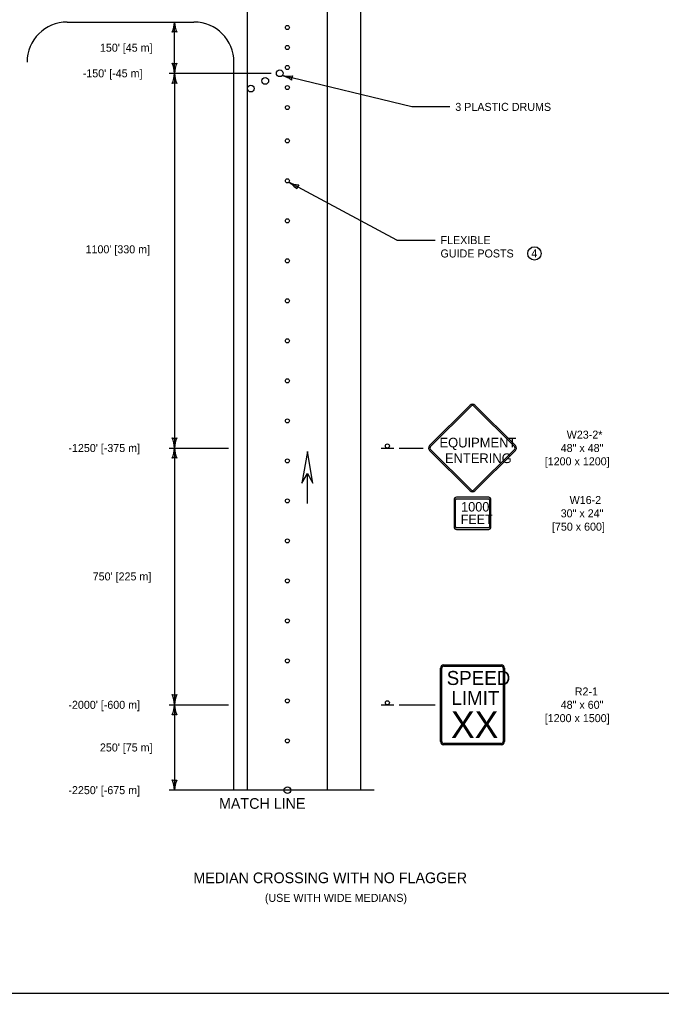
# Model space of a CAD drawing. Extents: x 49991.4 to 50021, y 49987.6 to 50011.4.
# Drawn here: x 50004.22 to 50009.03, y 49987.8 to 49995.1 of the extents above; entities that cross this region are included whole.
import ezdxf

# ---------------------------------------------------------------- set-up
doc = ezdxf.new("R2010")
doc.units = 0
for name, color, linetype in [('Level 1', 7, 'Continuous'), ('Level 2', 7, 'Continuous'), ('Level 3', 7, 'Continuous'), ('Level 6', 7, 'Continuous')]:
    doc.layers.add(name, color=color, linetype=linetype)

msp = doc.modelspace()

# ---------------------------------------------------------------- linework, layer by layer
at = {"layer": 'Level 1'}
for p, q in [((50005.9261, 49989.324), (50005.9261, 49998.3116)), ((50006.5261, 49989.324), (50006.5261, 49998.3116)), ((50006.7761, 49989.324), (50006.7761, 49998.3116)), ((50004.5755, 49995.0842), (50005.5261, 49995.0842)), ((50005.8261, 49989.324), (50005.8261, 49994.7842)), ((50005.3807, 49994.7), (50005.3807, 49993.9384)), ((50007.5963, 49992.2118), (50007.2922, 49991.9078)), ((50007.6033, 49992.2048), (50007.2993, 49991.9006)), ((50007.9286, 49991.9006), (50007.6246, 49992.2048)), ((50007.9357, 49991.9078), (50007.6316, 49992.2118)), ((50006.9281, 49991.89), (50007.0241, 49991.89)), ((50007.2922, 49991.8724), (50007.5963, 49991.5684)), ((50007.2993, 49991.8794), (50007.6033, 49991.5754)), ((50007.6246, 49991.5754), (50007.9286, 49991.8794)), ((50007.6316, 49991.5684), (50007.9357, 49991.8724)), ((50006.3758, 49991.4727), (50006.3758, 49991.6987)), ((50006.3761, 49991.4727), (50006.3761, 49991.6987)), ((50007.4757, 49991.5008), (50007.4757, 49991.2992)), ((50007.4872, 49991.2992), (50007.4872, 49991.5008)), ((50007.735, 49991.521), (50007.493, 49991.521)), ((50007.493, 49991.5076), (50007.735, 49991.5076)), ((50007.7407, 49991.5008), (50007.7407, 49991.2992)), ((50007.7522, 49991.2992), (50007.7522, 49991.5008)), ((50007.735, 49991.2925), (50007.493, 49991.2925)), ((50007.493, 49991.2791), (50007.735, 49991.2791)), ((50007.374, 49989.689), (50007.374, 49990.239)), ((50007.384, 49989.689), (50007.384, 49990.239)), ((50007.399, 49990.264), (50007.829, 49990.264)), ((50007.399, 49990.254), (50007.829, 49990.254)), ((50007.844, 49990.239), (50007.844, 49989.689)), ((50007.854, 49990.239), (50007.854, 49989.689)), ((50006.9281, 49989.964), (50007.0241, 49989.964)), ((50007.829, 49989.674), (50007.399, 49989.674)), ((50007.829, 49989.664), (50007.399, 49989.664))]:
    msp.add_line(p, q, dxfattribs=at)
for points in [[(49999.3835, 49998.9992), (50016.7501, 49998.9992), (50016.7501, 49987.7988), (49999.3835, 49987.7988)], [(50006.4178, 49991.6263), (50006.3761, 49991.8629), (50006.3342, 49991.6263), (50006.3761, 49991.6985)]]:
    msp.add_lwpolyline(points, close=True, dxfattribs=at)
for centre, radius in [((50006.2261, 49995.0436), 0.015), ((50006.2261, 49994.8936), 0.015), ((50006.2261, 49994.7436), 0.015), ((50006.1688, 49994.7), 0.025), ((50006.0605, 49994.6427), 0.025), ((50005.9523, 49994.5853), 0.025), ((50006.2261, 49994.5936), 0.015), ((50006.2261, 49994.4436), 0.015), ((50006.2261, 49994.4436), 0.015), ((50006.2261, 49994.1937), 0.015), ((50006.2261, 49993.8937), 0.015), ((50006.2261, 49993.5937), 0.015), ((50006.2261, 49993.2937), 0.015), ((50006.2261, 49992.9937), 0.015), ((50006.2261, 49992.6937), 0.015), ((50006.2261, 49992.3937), 0.015), ((50006.2261, 49992.0937), 0.015), ((50006.9761, 49991.9052), 0.0152), ((50006.2261, 49991.7937), 0.015), ((50006.2261, 49991.4937), 0.015), ((50006.2261, 49991.1937), 0.015), ((50006.2261, 49990.8937), 0.015), ((50006.2261, 49990.5937), 0.015), ((50006.2261, 49990.2937), 0.015), ((50006.2261, 49989.9937), 0.015), ((50006.2261, 49989.9937), 0.015), ((50006.9761, 49989.9792), 0.0152), ((50006.2261, 49989.6937), 0.015), ((50006.2261, 49989.6937), 0.015), ((50006.2264, 49989.3245), 0.025)]:
    msp.add_circle(centre, radius, dxfattribs=at)
for centre, radius, start, end in [((50004.5755, 49994.7843), 0.3, 90, 180), ((50005.5261, 49994.7843), 0.3, 0, 90), ((50007.614, 49992.1941), 0.025, 45, 135), ((50007.614, 49992.1941), 0.015, 45, 135), ((50007.3099, 49991.89), 0.025, 135, 225), ((50007.3099, 49991.89), 0.015, 135, 225), ((50007.918, 49991.89), 0.015, 315, 45.00024), ((50007.918, 49991.89), 0.025, 315, 45.00024), ((50007.614, 49991.586), 0.025, 225, 314.99957), ((50007.614, 49991.586), 0.015, 225, 314.99957), ((50007.3989, 49990.2389), 0.025, 90, 180), ((50007.3989, 49990.2389), 0.015, 90, 180), ((50007.8289, 49990.2389), 0.025, 0, 90), ((50007.8289, 49990.2389), 0.015, 0, 90), ((50007.3989, 49989.6889), 0.025, 180, 270), ((50007.3989, 49989.6889), 0.015, 180, 270), ((50007.8289, 49989.6889), 0.025, 270, 0), ((50007.8289, 49989.6889), 0.015, 270, 0)]:
    msp.add_arc(centre, radius, start, end, dxfattribs=at)
for centre, major_axis, start_param, end_param in [((50007.493, 49991.5008), (0, 0.0202), 0, 1.570796), ((50007.493, 49991.5008), (0, 0.00672), 0, 1.570796), ((50007.735, 49991.5008), (0, 0.0202), 4.712389, 6.283185), ((50007.735, 49991.5008), (0, 0.00672), 4.712389, 6.283185), ((50007.493, 49991.2992), (0, -0.0202), 4.712389, 6.283185), ((50007.493, 49991.2992), (0, -0.00672), 4.712389, 6.283185), ((50007.735, 49991.2992), (0, -0.00672), 0, 1.570796), ((50007.735, 49991.2992), (0, -0.0202), 0, 1.570796)]:
    msp.add_ellipse(centre, major_axis=major_axis, ratio=0.857375, start_param=start_param, end_param=end_param, dxfattribs=at)
at = {"layer": 'Level 2'}
msp.add_circle((50008.0781, 49993.3493), 0.05, dxfattribs=at)
at = {"layer": 'Level 3'}
for p, q in [((50005.3807, 49994.7), (50005.3807, 49995.0842)), ((50005.3407, 49994.7), (50006.1038, 49994.7)), ((50007.1581, 49994.4483), (50006.1874, 49994.6834)), ((50007.4448, 49994.4483), (50007.1581, 49994.4483)), ((50005.3807, 49993.9384), (50005.3807, 49991.89)), ((50007.0473, 49993.449), (50006.2367, 49993.8831)), ((50007.0473, 49993.449), (50007.3341, 49993.449)), ((50005.3407, 49991.89), (50005.7861, 49991.89)), ((50005.3807, 49991.89), (50005.3807, 49989.964)), ((50007.0641, 49991.89), (50007.2449, 49991.89)), ((50005.3407, 49989.964), (50005.7861, 49989.964)), ((50005.3807, 49989.964), (50005.3807, 49989.324)), ((50007.0641, 49989.964), (50007.334, 49989.964))]:
    msp.add_line(p, q, dxfattribs=at)
for centre, radius, start, end in [((50005.1585, 49995.0934), 0.2223, 337.45601, 357.63952), ((50005.6134, 49995.0957), 0.233, 182.82731, 202.07716), ((50005.3807, 49994.956), 0.0548, 72.13882, 107.86118), ((50005.3807, 49994.8283), 0.0548, 252.13882, 287.86118), ((50005.148, 49994.6886), 0.233, 2.82731, 22.07716), ((50005.6028, 49994.6909), 0.2223, 157.45601, 177.63952), ((50005.1585, 49994.7092), 0.2223, 337.45601, 357.63952), ((50005.6134, 49994.7115), 0.233, 182.82731, 202.07716), ((50005.3807, 49994.5718), 0.0548, 72.13882, 107.86118), ((50006.1262, 49994.4697), 0.2223, 53.83902, 74.02252), ((50006.231, 49994.9123), 0.233, 259.21032, 278.46017), ((50006.312, 49994.6532), 0.0548, 148.52182, 184.24419), ((50006.3318, 49994.084), 0.2223, 244.64868, 264.83219), ((50006.1183, 49993.6824), 0.233, 40.21104, 59.46089), ((50006.3502, 49993.8235), 0.0548, 134.42702, 170.14938), ((50005.3807, 49992.0183), 0.0548, 252.13882, 287.86118), ((50005.148, 49991.8786), 0.233, 2.82731, 22.07716), ((50005.6028, 49991.8809), 0.2223, 157.45601, 177.63952), ((50005.148, 49991.9015), 0.233, 337.92284, 357.17269), ((50005.6028, 49991.8992), 0.2223, 182.36048, 202.54399), ((50005.3807, 49991.7618), 0.0548, 72.13882, 107.86118), ((50005.3807, 49990.0923), 0.0548, 252.13882, 287.86118), ((50005.148, 49989.9526), 0.233, 2.82731, 22.07716), ((50005.6028, 49989.9549), 0.2223, 157.45601, 177.63952), ((50005.1585, 49989.9732), 0.2223, 337.45601, 357.63952), ((50005.6134, 49989.9755), 0.233, 182.82731, 202.07716), ((50005.3807, 49989.8358), 0.0548, 72.13882, 107.86118), ((50005.3807, 49989.4523), 0.0548, 252.13882, 287.86118), ((50005.148, 49989.3126), 0.233, 2.82731, 22.07716), ((50005.6028, 49989.3149), 0.2223, 157.45601, 177.63952)]:
    msp.add_arc(centre, radius, start, end, dxfattribs=at)
at = {"layer": 'Level 6'}
msp.add_line((50006.8761, 49989.324), (50005.3407, 49989.324), dxfattribs=at)

# ---------------------------------------------------------------- texts
at = {"layer": 'Level 1'}
for s, height, p in [('EQUIPMENT', 0.0725, (50007.3662, 49991.8943)), ('ENTERING', 0.0725, (50007.4069, 49991.7769)), ('1000', 0.07124, (50007.5282, 49991.4135)), ('FEET', 0.06989, (50007.5254, 49991.3194)), ('SPEED', 0.10512, (50007.4203, 49990.1127)), ('LIMIT', 0.10512, (50007.4557, 49989.9625)), ('XX', 0.1989, (50007.4525, 49989.7153))]:
    msp.add_text(s, height=height, dxfattribs=at).set_placement(p)
at = {"layer": 'Level 2'}
for s, height, p in [("150' [45 m]", 0.06, (50004.8212, 49994.8621)), ("-150' [-45 m]", 0.06, (50004.6926, 49994.67)), ('3 PLASTIC DRUMS', 0.06, (50007.4848, 49994.4183)), ('FLEXIBLE', 0.06, (50007.3741, 49993.419)), ("1100' [330 m]", 0.06, (50004.7134, 49993.3502)), ('GUIDE POSTS', 0.06, (50007.3741, 49993.319)), ('4', 0.06, (50008.0541, 49993.3193)), ('W23-2*', 0.06, (50008.3199, 49991.96)), ("-1250' [-375 m]", 0.06, (50004.5849, 49991.86)), ('48" x 48"', 0.06, (50008.2747, 49991.86)), ('[1200 x 1200]', 0.06, (50008.1552, 49991.76)), ('W16-2', 0.06, (50008.3416, 49991.47)), ('30" x 24"', 0.06, (50008.2747, 49991.37)), ('[750 x 600]', 0.06, (50008.2091, 49991.27)), ("750' [225 m]", 0.06, (50004.7673, 49990.897)), ('R2-1', 0.06, (50008.3802, 49990.034)), ("-2000' [-600 m]", 0.06, (50004.5849, 49989.934)), ('48" x 60"', 0.06, (50008.2747, 49989.934)), ('[1200 x 1500]', 0.06, (50008.1552, 49989.834)), ("250' [75 m]", 0.06, (50004.8212, 49989.614)), ("-2250' [-675 m]", 0.06, (50004.5849, 49989.294)), ('MATCH LINE', 0.08, (50005.7138, 49989.184)), ('MEDIAN CROSSING WITH NO FLAGGER', 0.08, (50005.5221, 49988.6264)), ('(USE WITH WIDE MEDIANS)', 0.06, (50006.0575, 49988.4864))]:
    msp.add_text(s, height=height, dxfattribs=at).set_placement(p)

doc.saveas('drawing.dxf')
